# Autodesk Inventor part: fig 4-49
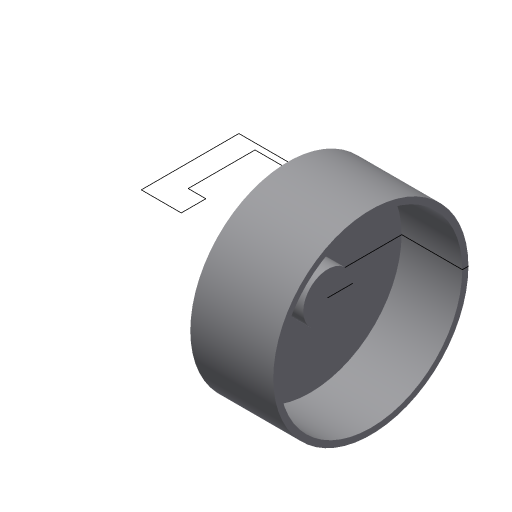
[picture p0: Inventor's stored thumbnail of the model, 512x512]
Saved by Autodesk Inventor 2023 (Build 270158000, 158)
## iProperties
Created: 2004-05
Part Number: fig 4-49
Document SubType Name: Modeling
Designer: CADCIM Technologies
Manufacturer: Standard
Standards Organization: Custom
Density: 1 g/cm^3
Material: Generic
Appearance: Default
Author: CADCIM Technologies
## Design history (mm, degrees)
sketch "Sketch1"
  geometry: L1 (37.08, 12.209)-(23.643, 12.209); L2 (23.643, 12.209)-(23.643, 45.026); L3 (23.643, 45.026)-(51.55, 45.026); L4 (51.55, 45.026)-(51.55, 42.959); L5 (51.55, 42.959)-(31.137, 42.959); L6 (31.137, 42.959)-(31.137, 20.478); L7 (31.137, 20.478)-(37.08, 20.478); L8 (37.08, 20.478)-(37.08, 12.209); L9 (86.437, 12.209)-(73, 12.209); L10 (73, 12.209)-(73, 45.026); L11 (73, 45.026)-(100.907, 45.026); L12 (100.907, 45.026)-(100.907, 42.959); L13 (100.907, 42.959)-(80.494, 42.959); L14 (80.494, 42.959)-(80.494, 20.478); L15 (80.494, 20.478)-(86.437, 20.478); L16 (86.437, 20.478)-(86.437, 12.209)
  constraints: 32 end point, 12 parallel, 2 horizontal, 2 perpendicular
revolve "Revolution1" sketch "Sketch1" stored, may be unused: angle "d0" = 90 deg
body "Solid1"
